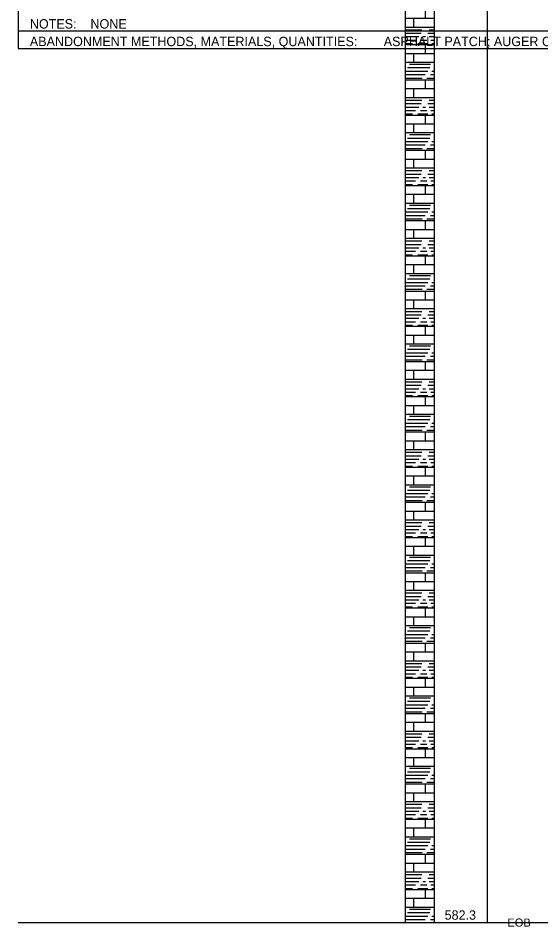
# Model space of a CAD drawing. Extents: x 0 to 0.83, y -0.65 to 1.27.
# Drawn here: x 0 to 0.372, y -0.649 to -0.003 of the extents above; entities that cross this region are included whole.
import ezdxf

# ---------------------------------------------------------------- set-up
doc = ezdxf.new("R2010")
doc.units = 0

msp = doc.modelspace()

# ---------------------------------------------------------------- linework, layer by layer
for points in [[(0.29583, 1.22083), (0.29583, -0.64575)], [(0.29583, 1.22083), (0.29583, -0.64575)], [(0.33333, 1.22083), (0.33333, -0.64575)], [(0.33333, 1.22083), (0.33333, -0.64575)], [(0.275, 1.19583), (0.275, -0.64575)], [(0.275, 0.21525), (0.275, -0.64575)], [(0, 0.0875), (0, -0.025), (0.83333, -0.025), (0.83333, 0.0875)], [(0.28958, -0.0035), (0.28958, 0.00275)], [(0.275, -0.0035), (0.29583, -0.0035)], [(0.28125, -0.00975), (0.28125, -0.0035)], [(0, -0.0125), (0.83333, -0.0125)], [(0.275, -0.00975), (0.29583, -0.00975)], [(0.275, -0.01167), (0.28683, -0.01167)], [(0.29217, -0.01167), (0.29583, -0.01167)], [(0.275, -0.01417), (0.28642, -0.01417)], [(0.275, -0.01658), (0.28483, -0.01658)], [(0.275, -0.019), (0.28233, -0.019)], [(0.286, -0.019), (0.2905, -0.019)], [(0.28767, -0.01658), (0.28967, -0.01658)], [(0.29133, -0.01417), (0.29583, -0.01417)], [(0.29217, -0.01658), (0.29583, -0.01658)], [(0.29342, -0.019), (0.29583, -0.019)], [(0.275, -0.0215), (0.28033, -0.0215)], [(0.275, -0.02225), (0.29583, -0.02225)], [(0.284, -0.0215), (0.29133, -0.0215)], [(0.28958, -0.0285), (0.28958, -0.02225)], [(0.29417, -0.0215), (0.29583, -0.0215)], [(0.275, -0.0285), (0.29583, -0.0285)], [(0.28125, -0.03475), (0.28125, -0.0285)], [(0.275, -0.03475), (0.29583, -0.03475)], [(0.27667, -0.03858), (0.29258, -0.03858)], [(0.27825, -0.03617), (0.293, -0.03617)], [(0.29542, -0.03617), (0.29583, -0.03617)], [(0.275, -0.04108), (0.29133, -0.04108)], [(0.275, -0.0435), (0.28933, -0.0435)], [(0.293, -0.0435), (0.29583, -0.0435)], [(0.29417, -0.04108), (0.29583, -0.04108)], [(0.275, -0.046), (0.28725, -0.046)], [(0.275, -0.04725), (0.29583, -0.04725)], [(0.28958, -0.0535), (0.28958, -0.04725)], [(0.2905, -0.046), (0.29583, -0.046)], [(0.275, -0.0535), (0.29583, -0.0535)], [(0.28125, -0.05975), (0.28125, -0.0535)], [(0.275, -0.05975), (0.29583, -0.05975)], [(0.275, -0.06167), (0.28683, -0.06167)], [(0.275, -0.06417), (0.28642, -0.06417)], [(0.29133, -0.06417), (0.29583, -0.06417)], [(0.29217, -0.06167), (0.29583, -0.06167)], [(0.275, -0.06658), (0.28483, -0.06658)], [(0.275, -0.069), (0.28233, -0.069)], [(0.286, -0.069), (0.2905, -0.069)], [(0.28767, -0.06658), (0.28967, -0.06658)], [(0.29217, -0.06658), (0.29583, -0.06658)], [(0.29342, -0.069), (0.29583, -0.069)], [(0.275, -0.0715), (0.28033, -0.0715)], [(0.275, -0.07225), (0.29583, -0.07225)], [(0.284, -0.0715), (0.29133, -0.0715)], [(0.28958, -0.0785), (0.28958, -0.07225)], [(0.29417, -0.0715), (0.29583, -0.0715)], [(0.275, -0.0785), (0.29583, -0.0785)], [(0.28125, -0.08475), (0.28125, -0.0785)], [(0.275, -0.08475), (0.29583, -0.08475)], [(0.27667, -0.08858), (0.29258, -0.08858)], [(0.27825, -0.08617), (0.293, -0.08617)], [(0.29542, -0.08617), (0.29583, -0.08617)], [(0.275, -0.09108), (0.29133, -0.09108)], [(0.275, -0.0935), (0.28933, -0.0935)], [(0.275, -0.096), (0.28725, -0.096)], [(0.2905, -0.096), (0.29583, -0.096)], [(0.293, -0.0935), (0.29583, -0.0935)], [(0.29417, -0.09108), (0.29583, -0.09108)], [(0.275, -0.09725), (0.29583, -0.09725)], [(0.28958, -0.1035), (0.28958, -0.09725)], [(0.275, -0.1035), (0.29583, -0.1035)], [(0.28125, -0.10975), (0.28125, -0.1035)], [(0.275, -0.10975), (0.29583, -0.10975)], [(0.275, -0.11167), (0.28683, -0.11167)], [(0.275, -0.11417), (0.28642, -0.11417)], [(0.29133, -0.11417), (0.29583, -0.11417)], [(0.29217, -0.11167), (0.29583, -0.11167)], [(0.275, -0.11658), (0.28483, -0.11658)], [(0.275, -0.119), (0.28233, -0.119)], [(0.275, -0.1215), (0.28033, -0.1215)], [(0.275, -0.12225), (0.29583, -0.12225)], [(0.284, -0.1215), (0.29133, -0.1215)], [(0.286, -0.119), (0.2905, -0.119)], [(0.28767, -0.11658), (0.28967, -0.11658)], [(0.28958, -0.1285), (0.28958, -0.12225)], [(0.29217, -0.11658), (0.29583, -0.11658)], [(0.29342, -0.119), (0.29583, -0.119)], [(0.29417, -0.1215), (0.29583, -0.1215)], [(0.275, -0.1285), (0.29583, -0.1285)], [(0.28125, -0.13475), (0.28125, -0.1285)], [(0.275, -0.13475), (0.29583, -0.13475)], [(0.275, -0.14108), (0.29133, -0.14108)], [(0.27667, -0.13858), (0.29258, -0.13858)], [(0.27825, -0.13617), (0.293, -0.13617)], [(0.29417, -0.14108), (0.29583, -0.14108)], [(0.29542, -0.13617), (0.29583, -0.13617)], [(0.275, -0.1435), (0.28933, -0.1435)], [(0.275, -0.146), (0.28725, -0.146)], [(0.275, -0.14725), (0.29583, -0.14725)], [(0.28958, -0.1535), (0.28958, -0.14725)], [(0.2905, -0.146), (0.29583, -0.146)], [(0.293, -0.1435), (0.29583, -0.1435)], [(0.275, -0.1535), (0.29583, -0.1535)], [(0.28125, -0.15975), (0.28125, -0.1535)], [(0.275, -0.15975), (0.29583, -0.15975)], [(0.275, -0.16167), (0.28683, -0.16167)], [(0.275, -0.16417), (0.28642, -0.16417)], [(0.275, -0.16658), (0.28483, -0.16658)], [(0.28767, -0.16658), (0.28967, -0.16658)], [(0.29133, -0.16417), (0.29583, -0.16417)], [(0.29217, -0.16167), (0.29583, -0.16167)], [(0.29217, -0.16658), (0.29583, -0.16658)], [(0.275, -0.169), (0.28233, -0.169)], [(0.275, -0.1715), (0.28033, -0.1715)], [(0.275, -0.17225), (0.29583, -0.17225)], [(0.284, -0.1715), (0.29133, -0.1715)], [(0.286, -0.169), (0.2905, -0.169)], [(0.28958, -0.1785), (0.28958, -0.17225)], [(0.29342, -0.169), (0.29583, -0.169)], [(0.29417, -0.1715), (0.29583, -0.1715)], [(0.275, -0.1785), (0.29583, -0.1785)], [(0.28125, -0.18475), (0.28125, -0.1785)], [(0.275, -0.18475), (0.29583, -0.18475)], [(0.27825, -0.18617), (0.293, -0.18617)], [(0.29542, -0.18617), (0.29583, -0.18617)], [(0.275, -0.19108), (0.29133, -0.19108)], [(0.275, -0.1935), (0.28933, -0.1935)], [(0.27667, -0.18858), (0.29258, -0.18858)], [(0.293, -0.1935), (0.29583, -0.1935)], [(0.29417, -0.19108), (0.29583, -0.19108)], [(0.275, -0.196), (0.28725, -0.196)], [(0.275, -0.19725), (0.29583, -0.19725)], [(0.28958, -0.2035), (0.28958, -0.19725)], [(0.2905, -0.196), (0.29583, -0.196)], [(0.275, -0.2035), (0.29583, -0.2035)], [(0.28125, -0.20975), (0.28125, -0.2035)], [(0.275, -0.20975), (0.29583, -0.20975)], [(0.275, -0.21167), (0.28683, -0.21167)], [(0.29217, -0.21167), (0.29583, -0.21167)], [(0.275, -0.21417), (0.28642, -0.21417)], [(0.275, -0.21658), (0.28483, -0.21658)], [(0.275, -0.219), (0.28233, -0.219)], [(0.286, -0.219), (0.2905, -0.219)], [(0.28767, -0.21658), (0.28967, -0.21658)], [(0.29133, -0.21417), (0.29583, -0.21417)], [(0.29217, -0.21658), (0.29583, -0.21658)], [(0.29342, -0.219), (0.29583, -0.219)], [(0.275, -0.2215), (0.28033, -0.2215)], [(0.275, -0.22225), (0.29583, -0.22225)], [(0.284, -0.2215), (0.29133, -0.2215)], [(0.28958, -0.2285), (0.28958, -0.22225)], [(0.29417, -0.2215), (0.29583, -0.2215)], [(0.275, -0.2285), (0.29583, -0.2285)], [(0.28125, -0.23475), (0.28125, -0.2285)], [(0.275, -0.23475), (0.29583, -0.23475)], [(0.27667, -0.23858), (0.29258, -0.23858)], [(0.27825, -0.23617), (0.293, -0.23617)], [(0.29542, -0.23617), (0.29583, -0.23617)], [(0.275, -0.24108), (0.29133, -0.24108)], [(0.275, -0.2435), (0.28933, -0.2435)], [(0.293, -0.2435), (0.29583, -0.2435)], [(0.29417, -0.24108), (0.29583, -0.24108)], [(0.275, -0.246), (0.28725, -0.246)], [(0.275, -0.24725), (0.29583, -0.24725)], [(0.28958, -0.2535), (0.28958, -0.24725)], [(0.2905, -0.246), (0.29583, -0.246)], [(0.275, -0.2535), (0.29583, -0.2535)], [(0.28125, -0.25975), (0.28125, -0.2535)], [(0.275, -0.25975), (0.29583, -0.25975)], [(0.275, -0.26167), (0.28683, -0.26167)], [(0.275, -0.26417), (0.28642, -0.26417)], [(0.29133, -0.26417), (0.29583, -0.26417)], [(0.29217, -0.26167), (0.29583, -0.26167)], [(0.275, -0.26658), (0.28483, -0.26658)], [(0.275, -0.269), (0.28233, -0.269)], [(0.286, -0.269), (0.2905, -0.269)], [(0.28767, -0.26658), (0.28967, -0.26658)], [(0.29217, -0.26658), (0.29583, -0.26658)], [(0.29342, -0.269), (0.29583, -0.269)], [(0.275, -0.2715), (0.28033, -0.2715)], [(0.275, -0.27225), (0.29583, -0.27225)], [(0.284, -0.2715), (0.29133, -0.2715)], [(0.28958, -0.2785), (0.28958, -0.27225)], [(0.29417, -0.2715), (0.29583, -0.2715)], [(0.275, -0.2785), (0.29583, -0.2785)], [(0.28125, -0.28475), (0.28125, -0.2785)], [(0.275, -0.28475), (0.29583, -0.28475)], [(0.27667, -0.28858), (0.29258, -0.28858)], [(0.27825, -0.28617), (0.293, -0.28617)], [(0.29542, -0.28617), (0.29583, -0.28617)], [(0.275, -0.29108), (0.29133, -0.29108)], [(0.275, -0.2935), (0.28933, -0.2935)], [(0.275, -0.296), (0.28725, -0.296)], [(0.2905, -0.296), (0.29583, -0.296)], [(0.293, -0.2935), (0.29583, -0.2935)], [(0.29417, -0.29108), (0.29583, -0.29108)], [(0.275, -0.29725), (0.29583, -0.29725)], [(0.28958, -0.3035), (0.28958, -0.29725)], [(0.275, -0.3035), (0.29583, -0.3035)], [(0.28125, -0.30975), (0.28125, -0.3035)], [(0.275, -0.30975), (0.29583, -0.30975)], [(0.275, -0.31167), (0.28683, -0.31167)], [(0.275, -0.31417), (0.28642, -0.31417)], [(0.29133, -0.31417), (0.29583, -0.31417)], [(0.29217, -0.31167), (0.29583, -0.31167)], [(0.275, -0.31658), (0.28483, -0.31658)], [(0.275, -0.319), (0.28233, -0.319)], [(0.275, -0.3215), (0.28033, -0.3215)], [(0.275, -0.32225), (0.29583, -0.32225)], [(0.284, -0.3215), (0.29133, -0.3215)], [(0.286, -0.319), (0.2905, -0.319)], [(0.28767, -0.31658), (0.28967, -0.31658)], [(0.28958, -0.3285), (0.28958, -0.32225)], [(0.29217, -0.31658), (0.29583, -0.31658)], [(0.29342, -0.319), (0.29583, -0.319)], [(0.29417, -0.3215), (0.29583, -0.3215)], [(0.275, -0.3285), (0.29583, -0.3285)], [(0.28125, -0.33475), (0.28125, -0.3285)], [(0.275, -0.33475), (0.29583, -0.33475)], [(0.275, -0.34108), (0.29133, -0.34108)], [(0.27667, -0.33858), (0.29258, -0.33858)], [(0.27825, -0.33617), (0.293, -0.33617)], [(0.29417, -0.34108), (0.29583, -0.34108)], [(0.29542, -0.33617), (0.29583, -0.33617)], [(0.275, -0.3435), (0.28933, -0.3435)], [(0.275, -0.346), (0.28725, -0.346)], [(0.275, -0.34725), (0.29583, -0.34725)], [(0.28958, -0.3535), (0.28958, -0.34725)], [(0.2905, -0.346), (0.29583, -0.346)], [(0.293, -0.3435), (0.29583, -0.3435)], [(0.275, -0.3535), (0.29583, -0.3535)], [(0.28125, -0.35975), (0.28125, -0.3535)], [(0.275, -0.35975), (0.29583, -0.35975)], [(0.275, -0.36167), (0.28683, -0.36167)], [(0.275, -0.36417), (0.28642, -0.36417)], [(0.275, -0.36658), (0.28483, -0.36658)], [(0.28767, -0.36658), (0.28967, -0.36658)], [(0.29133, -0.36417), (0.29583, -0.36417)], [(0.29217, -0.36167), (0.29583, -0.36167)], [(0.29217, -0.36658), (0.29583, -0.36658)], [(0.275, -0.369), (0.28233, -0.369)], [(0.275, -0.3715), (0.28033, -0.3715)], [(0.275, -0.37225), (0.29583, -0.37225)], [(0.284, -0.3715), (0.29133, -0.3715)], [(0.286, -0.369), (0.2905, -0.369)], [(0.28958, -0.3785), (0.28958, -0.37225)], [(0.29342, -0.369), (0.29583, -0.369)], [(0.29417, -0.3715), (0.29583, -0.3715)], [(0.275, -0.3785), (0.29583, -0.3785)], [(0.28125, -0.38475), (0.28125, -0.3785)], [(0.275, -0.38475), (0.29583, -0.38475)], [(0.27825, -0.38617), (0.293, -0.38617)], [(0.29542, -0.38617), (0.29583, -0.38617)], [(0.275, -0.39108), (0.29133, -0.39108)], [(0.275, -0.3935), (0.28933, -0.3935)], [(0.27667, -0.38858), (0.29258, -0.38858)], [(0.293, -0.3935), (0.29583, -0.3935)], [(0.29417, -0.39108), (0.29583, -0.39108)], [(0.275, -0.396), (0.28725, -0.396)], [(0.275, -0.39725), (0.29583, -0.39725)], [(0.28958, -0.4035), (0.28958, -0.39725)], [(0.2905, -0.396), (0.29583, -0.396)], [(0.275, -0.4035), (0.29583, -0.4035)], [(0.28125, -0.40975), (0.28125, -0.4035)], [(0.275, -0.40975), (0.29583, -0.40975)], [(0.275, -0.41167), (0.28683, -0.41167)], [(0.29217, -0.41167), (0.29583, -0.41167)], [(0.275, -0.41417), (0.28642, -0.41417)], [(0.275, -0.41658), (0.28483, -0.41658)], [(0.275, -0.419), (0.28233, -0.419)], [(0.286, -0.419), (0.2905, -0.419)], [(0.28767, -0.41658), (0.28967, -0.41658)], [(0.29133, -0.41417), (0.29583, -0.41417)], [(0.29217, -0.41658), (0.29583, -0.41658)], [(0.29342, -0.419), (0.29583, -0.419)], [(0.275, -0.4215), (0.28033, -0.4215)], [(0.275, -0.42225), (0.29583, -0.42225)], [(0.284, -0.4215), (0.29133, -0.4215)], [(0.28958, -0.4285), (0.28958, -0.42225)], [(0.29417, -0.4215), (0.29583, -0.4215)], [(0.275, -0.4285), (0.29583, -0.4285)], [(0.28125, -0.43475), (0.28125, -0.4285)], [(0.275, -0.43475), (0.29583, -0.43475)], [(0.27667, -0.43858), (0.29258, -0.43858)], [(0.27825, -0.43617), (0.293, -0.43617)], [(0.29542, -0.43617), (0.29583, -0.43617)], [(0.275, -0.44108), (0.29133, -0.44108)], [(0.275, -0.4435), (0.28933, -0.4435)], [(0.293, -0.4435), (0.29583, -0.4435)], [(0.29417, -0.44108), (0.29583, -0.44108)], [(0.275, -0.446), (0.28725, -0.446)], [(0.275, -0.44725), (0.29583, -0.44725)], [(0.28958, -0.4535), (0.28958, -0.44725)], [(0.2905, -0.446), (0.29583, -0.446)], [(0.275, -0.4535), (0.29583, -0.4535)], [(0.28125, -0.45975), (0.28125, -0.4535)], [(0.275, -0.45975), (0.29583, -0.45975)], [(0.275, -0.46167), (0.28683, -0.46167)], [(0.275, -0.46417), (0.28642, -0.46417)], [(0.29133, -0.46417), (0.29583, -0.46417)], [(0.29217, -0.46167), (0.29583, -0.46167)], [(0.275, -0.46658), (0.28483, -0.46658)], [(0.275, -0.469), (0.28233, -0.469)], [(0.286, -0.469), (0.2905, -0.469)], [(0.28767, -0.46658), (0.28967, -0.46658)], [(0.29217, -0.46658), (0.29583, -0.46658)], [(0.29342, -0.469), (0.29583, -0.469)], [(0.275, -0.4715), (0.28033, -0.4715)], [(0.275, -0.47225), (0.29583, -0.47225)], [(0.284, -0.4715), (0.29133, -0.4715)], [(0.28958, -0.4785), (0.28958, -0.47225)], [(0.29417, -0.4715), (0.29583, -0.4715)], [(0.275, -0.4785), (0.29583, -0.4785)], [(0.28125, -0.48475), (0.28125, -0.4785)], [(0.275, -0.48475), (0.29583, -0.48475)], [(0.27667, -0.48858), (0.29258, -0.48858)], [(0.27825, -0.48617), (0.293, -0.48617)], [(0.29542, -0.48617), (0.29583, -0.48617)], [(0.275, -0.49108), (0.29133, -0.49108)], [(0.275, -0.4935), (0.28933, -0.4935)], [(0.275, -0.496), (0.28725, -0.496)], [(0.2905, -0.496), (0.29583, -0.496)], [(0.293, -0.4935), (0.29583, -0.4935)], [(0.29417, -0.49108), (0.29583, -0.49108)], [(0.275, -0.49725), (0.29583, -0.49725)], [(0.28958, -0.5035), (0.28958, -0.49725)], [(0.275, -0.5035), (0.29583, -0.5035)], [(0.275, -0.50975), (0.29583, -0.50975)], [(0.28125, -0.50975), (0.28125, -0.5035)], [(0.275, -0.51167), (0.28683, -0.51167)], [(0.275, -0.51417), (0.28642, -0.51417)], [(0.29133, -0.51417), (0.29583, -0.51417)], [(0.29217, -0.51167), (0.29583, -0.51167)], [(0.275, -0.51658), (0.28483, -0.51658)], [(0.275, -0.519), (0.28233, -0.519)], [(0.275, -0.5215), (0.28033, -0.5215)], [(0.275, -0.52225), (0.29583, -0.52225)], [(0.284, -0.5215), (0.29133, -0.5215)], [(0.286, -0.519), (0.2905, -0.519)], [(0.28767, -0.51658), (0.28967, -0.51658)], [(0.28958, -0.5285), (0.28958, -0.52225)], [(0.29217, -0.51658), (0.29583, -0.51658)], [(0.29342, -0.519), (0.29583, -0.519)], [(0.29417, -0.5215), (0.29583, -0.5215)], [(0.275, -0.5285), (0.29583, -0.5285)], [(0.28125, -0.53475), (0.28125, -0.5285)], [(0.275, -0.53475), (0.29583, -0.53475)], [(0.275, -0.54108), (0.29133, -0.54108)], [(0.27667, -0.53858), (0.29258, -0.53858)], [(0.27825, -0.53617), (0.293, -0.53617)], [(0.29417, -0.54108), (0.29583, -0.54108)], [(0.29542, -0.53617), (0.29583, -0.53617)], [(0.275, -0.5435), (0.28933, -0.5435)], [(0.275, -0.546), (0.28725, -0.546)], [(0.275, -0.54725), (0.29583, -0.54725)], [(0.28958, -0.5535), (0.28958, -0.54725)], [(0.2905, -0.546), (0.29583, -0.546)], [(0.293, -0.5435), (0.29583, -0.5435)], [(0.275, -0.5535), (0.29583, -0.5535)], [(0.28125, -0.55975), (0.28125, -0.5535)], [(0.275, -0.55975), (0.29583, -0.55975)], [(0.275, -0.56167), (0.28683, -0.56167)], [(0.275, -0.56417), (0.28642, -0.56417)], [(0.275, -0.56658), (0.28483, -0.56658)], [(0.28767, -0.56658), (0.28967, -0.56658)], [(0.29133, -0.56417), (0.29583, -0.56417)], [(0.29217, -0.56167), (0.29583, -0.56167)], [(0.29217, -0.56658), (0.29583, -0.56658)], [(0.275, -0.569), (0.28233, -0.569)], [(0.275, -0.5715), (0.28033, -0.5715)], [(0.275, -0.57225), (0.29583, -0.57225)], [(0.284, -0.5715), (0.29133, -0.5715)], [(0.286, -0.569), (0.2905, -0.569)], [(0.28958, -0.5785), (0.28958, -0.57225)], [(0.29342, -0.569), (0.29583, -0.569)], [(0.29417, -0.5715), (0.29583, -0.5715)], [(0.275, -0.5785), (0.29583, -0.5785)], [(0.28125, -0.58475), (0.28125, -0.5785)], [(0.275, -0.58475), (0.29583, -0.58475)], [(0.27825, -0.58617), (0.293, -0.58617)], [(0.29542, -0.58617), (0.29583, -0.58617)], [(0.275, -0.59108), (0.29133, -0.59108)], [(0.275, -0.5935), (0.28933, -0.5935)], [(0.27667, -0.58858), (0.29258, -0.58858)], [(0.293, -0.5935), (0.29583, -0.5935)], [(0.29417, -0.59108), (0.29583, -0.59108)], [(0.275, -0.596), (0.28725, -0.596)], [(0.275, -0.59725), (0.29583, -0.59725)], [(0.28958, -0.6035), (0.28958, -0.59725)], [(0.2905, -0.596), (0.29583, -0.596)], [(0.275, -0.6035), (0.29583, -0.6035)], [(0.28125, -0.60975), (0.28125, -0.6035)], [(0.275, -0.60975), (0.29583, -0.60975)], [(0.275, -0.61167), (0.28683, -0.61167)], [(0.29217, -0.61167), (0.29583, -0.61167)], [(0.275, -0.61417), (0.28642, -0.61417)], [(0.275, -0.61658), (0.28483, -0.61658)], [(0.275, -0.619), (0.28233, -0.619)], [(0.286, -0.619), (0.2905, -0.619)], [(0.28767, -0.61658), (0.28967, -0.61658)], [(0.29133, -0.61417), (0.29583, -0.61417)], [(0.29217, -0.61658), (0.29583, -0.61658)], [(0.29342, -0.619), (0.29583, -0.619)], [(0.275, -0.6215), (0.28033, -0.6215)], [(0.275, -0.62225), (0.29583, -0.62225)], [(0.284, -0.6215), (0.29133, -0.6215)], [(0.28958, -0.6285), (0.28958, -0.62225)], [(0.29417, -0.6215), (0.29583, -0.6215)], [(0.275, -0.6285), (0.29583, -0.6285)], [(0.28125, -0.63475), (0.28125, -0.6285)], [(0.275, -0.63475), (0.29583, -0.63475)], [(0.27667, -0.63858), (0.29258, -0.63858)], [(0.27825, -0.63617), (0.293, -0.63617)], [(0.29542, -0.63617), (0.29583, -0.63617)], [(0.275, -0.64108), (0.29133, -0.64108)], [(0.275, -0.6435), (0.28933, -0.6435)], [(0.293, -0.6435), (0.29583, -0.6435)], [(0.29417, -0.64108), (0.29583, -0.64108)], [(0, -0.64575), (0.275, -0.64575)], [(0.275, -0.64575), (0.29583, -0.64575)], [(0.275, -0.64575), (0.29583, -0.64575)], [(0.29583, -0.64575), (0.33333, -0.64575)], [(0.33333, -0.64575), (0.37917, -0.64575)]]:
    msp.add_lwpolyline(points)

# ---------------------------------------------------------------- texts
for s, height, p in [('NOTES:', 0.006667, (0.00833, -0.01083)), ('NONE', 0.006667, (0.05139, -0.01083)), ('ABANDONMENT METHODS, MATERIALS, QUANTITIES:', 0.0066667, (0.00833, -0.02333)), ('ASPHALT PATCH; AUGER CUTTINGS MIXED WITH   BENTONITE CHIPS', 0.0066667, (0.25986, -0.02333)), ('582.3', 0.006667, (0.30314, -0.6437)), ('EOB', 0.005833, (0.34786, -0.64867))]:
    msp.add_text(s, height=height).set_placement(p)

doc.saveas('drawing.dxf')
